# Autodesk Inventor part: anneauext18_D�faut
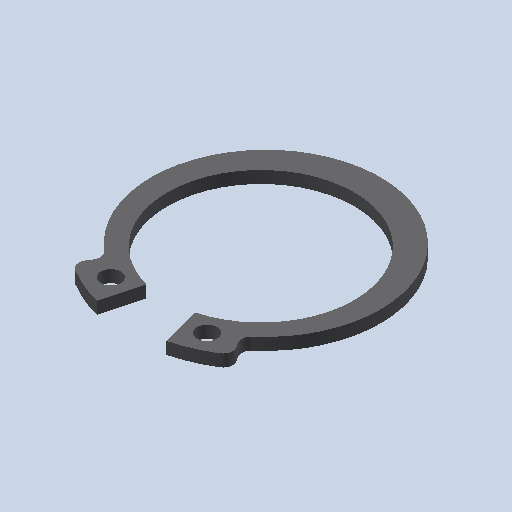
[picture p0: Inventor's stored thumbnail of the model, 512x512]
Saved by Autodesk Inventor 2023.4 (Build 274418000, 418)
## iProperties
Created: 2011-01
Part Number: anneauext18_D�faut
Document SubType Name: Modeling
Designer: eric
Density: 1 g/cm^3
Mass: 0.172049 g
Surface Area: 4.59869 cm^2
Volume: 0.172049 cm^3
Material: Générique
Appearance: Red
Author: eric
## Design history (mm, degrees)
feature "Base1"
node "Corps solides"
node "Corps surfaciques"
node "Solide1"
